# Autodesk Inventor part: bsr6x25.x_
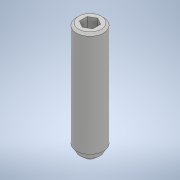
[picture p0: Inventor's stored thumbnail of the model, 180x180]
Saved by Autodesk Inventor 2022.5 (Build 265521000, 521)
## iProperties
Created: 2020-01
Part Number: bsr6x25.x_
Material: 一般
Document SubType Name: Modeling
Designer: ImaoCorp
Density: 1 g/cm^3
Appearance: 既定
Sending System: SOLIDWORKS 2018-2018316
MC: AMD64
MC_MODEL: Intel64 Family 6 Model 60 Stepping 3, GenuineIntel
OS: Windows_NT
FRU: Parasolid Version 30.0, build 310,  6- 8-2018
FORMAT: text
GUISE: transmit
KEY: bsr6x25
FILE: bsr6x25.x_t
DATE: Thu Jan 23 16:47:04 2020
Author: ImaoCorp
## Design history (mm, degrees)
feature "Base1"
node "ソリッド1"
